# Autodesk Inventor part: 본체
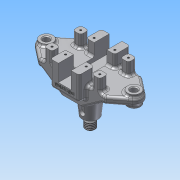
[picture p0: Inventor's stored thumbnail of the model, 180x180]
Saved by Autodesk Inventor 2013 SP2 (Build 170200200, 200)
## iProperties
Created: 2025-07
Part Number: 본체
Material: 알루미늄 6061
Document SubType Name: Modeling
Designer: a
Density: 2.71 g/cm^3
Mass: 328.836 g
Surface Area: 260.948 cm^2
Volume: 121.342 cm^3
Author: a
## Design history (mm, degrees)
sketch "스케치1"
  geometry: L1 (-41.804, 23)-(41.804, 23); L2 (41.804, 23)-(41.804, -23); L3 (41.804, -23)-(-41.804, -23); L4 (-41.804, -23)-(-41.804, 23); L5 (-41.804, 23)-(41.804, -23); L6 (41.804, 23)-(-41.804, -23); L7 (41.804, -23)-(61.157, -7.88); L8 (61.157, 7.88)-(41.804, 23); L9 (-41.804, -23)-(-61.157, -7.88); L10 (-41.804, 23)-(-61.157, 7.88); A1 r 10 centre (55, 0) between (61.157, -7.88) and (61.157, 7.88); A2 r 10 centre (-55, 0) between (-61.157, -7.88) and (-61.157, 7.88); 3 further points
  constraints: 20 end point, 4 midpoint, 4 point on circle, 4 tangent, 2 centre point, 2 horizontal alignment, 2 parallel, 1 horizontal, 1 perpendicular
  dimensions: "d0" = 46 distance of L3.end L1.start; "d4" = 110 distance of A2.centre A1.centre; "d5" = 55 distance of point (0, 0) A2.centre; "d6" = 76 deg angle of L10 L9; "d7" = 76 deg angle of L8 L7; "d8" = 20 diameter of A1
extrude "돌출1" new body sketch "스케치1" stored distance "d9" = 9; taper "d10" = 0 deg
sketch "스케치2"
  geometry: C1 r 8 at (-55, 0); C2 r 8 at (55, 0); A1 r 10 centre (-55, 0) between (-61.157, 7.88) and (-61.157, -7.88) reference; A2 r 10 centre (55, 0) between (61.157, -7.88) and (61.157, 7.88) reference; 1 further point
  constraints: 2 centre point, 2 coincident
  dimensions: "d11" = 16 diameter of C1; "d13" = 16 diameter of C2
extrude "돌출2" join sketch "스케치2" distance "d14" = 3; taper "d15" = 0 deg
extrude "돌출3" join sketch "스케치2" distance "d16" = 12; taper "d17" = 0 deg
hole "구멍1" diameter "d20" = 8; stored, may be unused: countersink angle "d24" = 90 deg, drill point angle "d26" = 118 deg; dims "d18" = 10, "d19" = 10, "d21" = 6, "d22" = 4, "d23" = 2, "d25" = 8
hole "구멍2" diameter "d29" = 8; stored, may be unused: countersink angle "d33" = 90 deg, drill point angle "d35" = 118 deg; dims "d27" = 10, "d28" = 10, "d30" = 6, "d31" = 4, "d32" = 2, "d34" = 8
chamfer "모따기1" distance "d36" = 1; stored, may be unused: second distance "d37" = 2, angle "d38" = 45 deg
chamfer "모따기2" distance "d39" = 1; stored, may be unused: second distance "d40" = 2, angle "d41" = 45 deg
chamfer "모따기3" distance "d42" = 1; stored, may be unused: second distance "d43" = 2, angle "d44" = 45 deg
chamfer "모따기4" distance "d45" = 1; stored, may be unused: second distance "d46" = 2, angle "d47" = 45 deg
sketch "스케치3"
  geometry: L1 (-41.804, -23)-(41.804, -23) reference; L2 (41.804, 23)-(-41.804, 23) reference; L3 (-35, -23)-(-25, -23); L4 (-25, -23)-(-25, -13); L5 (-25, -13)-(-35, -13); L6 (-35, -13)-(-35, -23); L7 (0, 23)-(0, -23); L8 (-55, 0)-(55, 0); L9 (-30, -13)-(-30, -23); L10 (-35, -18)-(-25, -18); L11 (61.157, -7.88)-(41.804, -23); L12 (25, -13)-(35, -13); L13 (35, -13)-(35, -23); L14 (35, -18)-(25, -18); L15 (30, -13)-(30, -23); L16 (25, -23)-(25, -13); L17 (35, -23)-(25, -23); L18 (41.804, -23)-(-41.804, -23); L19 (-25, 23)-(-25, 13); L20 (-30, 13)-(-30, 23); L21 (-25, 13)-(-35, 13); L22 (-35, 13)-(-35, 23); L23 (-35, 23)-(-25, 23); L24 (-35, 18)-(-25, 18); L25 (30, 13)-(30, 23); L26 (25, 13)-(35, 13); L27 (35, 13)-(35, 23); L28 (35, 18)-(25, 18); L29 (35, 23)-(25, 23); L30 (25, 23)-(25, 13); L31 (0, -23)-(0, 23); L32 (-41.804, 23)-(41.804, 23); L33 (41.804, 23)-(-41.804, 23); A1 r 10 centre (-55, 0) between (-61.157, 7.88) and (-61.157, -7.88) reference; A2 r 10 centre (55, 0) between (61.157, -7.88) and (61.157, 7.88) reference; 1 further point
  constraints: 62 end point, 32 symmetric about line, 6 midpoint, 4 point on line, 2 parallel, 2 perpendicular, 1 horizontal
  dimensions: "d48" = 10 distance of L4.end L5.end; "d50" = 10 distance of L3.end L4.end; "d51" = 30 distance between parallel lines of L7 L9
extrude "돌출4" join sketch "스케치3" distance "d52" = 16; taper "d53" = 0 deg
sketch "스케치4"
  geometry: L1 (-18, 32)-(18, 32); L2 (18, 32)-(18, 13); L3 (18, 13)-(-18, 13); L4 (-18, 13)-(-18, 32); L5 (-18, -13)-(18, -13); L6 (18, -13)-(18, -32); L7 (18, -32)-(-18, -32); L8 (-18, -32)-(-18, -13); 3 further points
  constraints: 16 end point, 4 parallel, 2 horizontal, 2 midpoint, 2 perpendicular, 2 vertical alignment
  dimensions: "d54" = 36 distance of L1.start L1.end; "d56" = 36 distance of L6.end L7.end; "d57" = 64 distance between parallel lines of L7 L1; "d58" = 32 distance of point (0, 0) point (0, 32); "d59" = 26 distance between parallel lines of L5 L3; "d60" = 13 distance from line of point (0, 0) L3
extrude "돌출5" join sketch "스케치4" distance "d61" = 16; taper "d63" = 0 deg; dims "d62" = 15, "d64" = 0
sketch "스케치5"
  geometry: L1 (0, 0)-(36, 0) reference; L2 (10, 0)-(26, 0); L3 (26, 0)-(26, -21); L4 (26, -21)-(10, -21); L5 (10, -21)-(10, 0); 2 further points
  constraints: 8 end point, 2 midpoint, 2 parallel, 1 horizontal, 1 perpendicular, 1 vertical alignment
  dimensions: "d65" = 16 distance of L2.start L2.end; "d67" = 21 distance of L4.end L2.start
extrude "돌출6" cut sketch "스케치5" stored distance "d68" = 16; taper "d69" = 0 deg
sketch "스케치6"
  geometry: L1 (60, -7.5)-(59, -6.5) reference; L2 (59, -6.5)-(59, 6.5) reference; L3 (59, 6.5)-(60, 7.5) reference; L4 (60, 7.5)-(63, 7.5) reference; L5 (63, 7.5)-(63, 4.5) reference; L6 (63, 4.5)-(65, 4.5) reference; L7 (65, 4.5)-(65, -4.5) reference; L8 (65, -4.5)-(63, -4.5) reference; L9 (63, -4.5)-(63, -7.5) reference; L10 (63, -7.5)-(60, -7.5) reference; L11 (-59, -6.5)-(-60, -7.5) reference; L12 (-60, -7.5)-(-63, -7.5) reference; L13 (-63, -7.5)-(-63, -4.5) reference; L14 (-63, -4.5)-(-65, -4.5) reference; L15 (-65, -4.5)-(-65, 4.5) reference; L16 (-65, 4.5)-(-63, 4.5) reference; L17 (-63, 4.5)-(-63, 7.5) reference; L18 (-63, 7.5)-(-60, 7.5) reference; L19 (-60, 7.5)-(-59, 6.5) reference; L20 (-59, 6.5)-(-59, -6.5) reference; L21 (-50, -7.5)-(-51, -6.5) reference; L22 (-51, -6.5)-(-51, 6.5) reference; L23 (-51, 6.5)-(-50, 7.5) reference; L24 (-50, 7.5)-(-47, 7.5) reference; L25 (-47, 7.5)-(-47, 4.5) reference; L26 (-47, 4.5)-(-8, 4.5) reference; L27 (-8, 4.5)-(-8, -0.5) reference; L28 (-8, -0.5)-(8, -0.5) reference; L29 (8, -0.5)-(8, 4.5) reference; L30 (8, 4.5)-(47, 4.5) reference; L31 (47, 4.5)-(47, 7.5) reference; L32 (47, 7.5)-(50, 7.5) reference; L33 (50, 7.5)-(51, 6.5) reference; L34 (51, 6.5)-(51, -6.5) reference; L35 (51, -6.5)-(50, -7.5) reference; L36 (50, -7.5)-(47, -7.5) reference; L37 (47, -7.5)-(47, -4.5) reference; L38 (47, -4.5)-(-47, -4.5) reference; L39 (-47, -4.5)-(-47, -7.5) reference; L40 (-47, -7.5)-(-50, -7.5) reference; L41 (-38.85, -4.5)-(-16, -20.5); L42 (-16, -20.5)-(16, -20.5); L43 (16, -20.5)-(38.85, -4.5); L44 (25, 20.5)-(35, 20.5) reference; L45 (-38.85, -4.5)-(38.85, -4.5); 2 further points
  constraints: 8 end point, 2 point on line, 1 collinear, 1 midpoint, 1 parallel, 1 vertical alignment
  dimensions: "d70" = 41 distance between parallel lines of L44 L42; "d71" = 35 deg angle of L42 L43; "d72" = 35 deg angle of L42 L41; "d73" = 32 distance of L41.end L42.end
extrude "돌출7" join sketch "스케치6" stored distance "d74" = 46; taper "d75" = 0 deg
sketch "스케치7"
  geometry: L1 (-10.5, 23)-(-10.5, 32) reference; L2 (-10.5, 32)-(-0.5, 32) reference; L3 (-0.5, 32)-(-0.5, -32) reference; L4 (-0.5, -32)-(-10.5, -32) reference; L5 (-10.5, -32)-(-10.5, -23) reference; L6 (-10.5, -23)-(-20.5, -23) reference; L7 (-20.5, -23)-(-20.5, 23) reference; L8 (-20.5, 23)-(-10.5, 23) reference; L9 (-20.5, 0)-(-47.5, 0); L10 (-20.5, 12.5)-(-24.5, 12.5); L11 (-24.5, 12.5)-(-47.5, 10); L12 (-47.5, 10)-(-47.5, 0); L13 (-20.5, 12.5)-(-20.5, 0); 1 further point
  constraints: 10 end point, 3 parallel, 1 midpoint, 1 perpendicular, 1 point on line
  dimensions: "d76" = 25 diameter of L10 L9; "d78" = 4 distance of L10.start L10.end; "d79" = 23 horizontal distance of L11.end L10.end; "d80" = 20 diameter of L11.end L9
revolve "회전1" sketch "스케치7" stored, may be unused: angle "d81" = 90 deg
sketch "스케치8"
  geometry: L1 (-10.5, 23)-(-10.5, 32) reference; L2 (-10.5, 32)-(-0.5, 32) reference; L3 (-0.5, 32)-(-0.5, -32) reference; L4 (-0.5, -32)-(-10.5, -32) reference; L5 (-10.5, -32)-(-10.5, -23) reference; L6 (-10.5, -23)-(-20.5, -23) reference; L7 (-20.5, -23)-(-20.5, -12.5) reference; L8 (-20.5, -12.5)-(-24.5, -12.5) reference; L9 (-24.5, -12.5)-(-47.5, -10) reference; L10 (-47.5, -10)-(-47.5, 10) reference; L11 (-47.5, 10)-(-24.5, 12.5) reference; L12 (-24.5, 12.5)-(-20.5, 12.5) reference; L13 (-20.5, 12.5)-(-20.5, 23) reference; L14 (-20.5, 23)-(-10.5, 23) reference; L15 (-47.5, 0)-(-61.5, 0); L16 (-47.5, 0)-(-47.5, 4.7); L17 (-47.5, 4.7)-(-50.5, 4.7); L18 (-50.5, 4.7)-(-52.752, 6); L19 (-52.752, 6)-(-61.5, 6); L20 (-61.5, 6)-(-61.5, 0); 1 further point
  constraints: 12 end point, 2 parallel, 2 perpendicular, 1 midpoint, 1 point on line
  dimensions: "d82" = 3 distance of L16.end L17.end; "d84" = 30 deg angle of L19 L18; "d86" = 9.4 diameter of L17 L15; "d87" = 41 distance between parallel lines of L13 L20; "d89" = 12 diameter of L19 L15
revolve "회전2" sketch "스케치8" stored, may be unused: angle "d90" = 90 deg
chamfer "모따기5" distance "d91" = 1; stored, may be unused: second distance "d92" = 2, angle "d93" = 45 deg
feature "스레드1" dims "d94" = 10, "d95" = 0
sketch "스케치9"
  geometry: L1 (-10.5, 23)-(-10.5, 32) reference; L2 (-10.5, 32)-(-0.5, 32) reference; L3 (-0.5, 32)-(-0.5, -32) reference; L4 (-0.5, -32)-(-10.5, -32) reference; L5 (-10.5, -32)-(-10.5, -23) reference; L6 (-10.5, -23)-(-20.5, -23) reference; L7 (-20.5, -23)-(-20.5, -12.5) reference; L8 (-20.5, -12.5)-(-24.5, -12.5) reference; L9 (-24.5, -12.5)-(-47.5, -10) reference; L10 (-47.5, -10)-(-47.5, -4.7) reference; L11 (-47.5, -4.7)-(-50.5, -4.7) reference; L12 (-50.5, -4.7)-(-52.752, -6) reference; L13 (-52.752, -6)-(-60.5, -6) reference; L14 (-60.5, -6)-(-61.5, -5) reference; L15 (-61.5, -5)-(-61.5, 5) reference; L16 (-61.5, 5)-(-60.5, 6) reference; L17 (-60.5, 6)-(-52.752, 6) reference; L18 (-52.752, 6)-(-50.5, 4.7) reference; L19 (-50.5, 4.7)-(-47.5, 4.7) reference; L20 (-47.5, 4.7)-(-47.5, 10) reference; L21 (-47.5, 10)-(-24.5, 12.5) reference; L22 (-24.5, 12.5)-(-20.5, 12.5) reference; L23 (-20.5, 12.5)-(-20.5, 23) reference; L24 (-20.5, 23)-(-10.5, 23) reference; L25 (-27.617, 12.161)-(-27.185, 8.185); L26 (-27.185, 8.185)-(-43.091, 6.456); L27 (-43.091, 6.456)-(-43.523, 10.432); L28 (-27.617, 12.161)-(-43.523, 10.432); 1 further point
  constraints: 8 end point, 2 perpendicular, 2 point on line, 1 collinear, 1 parallel
  dimensions: "d96" = 4 distance between parallel lines of L21 L26; "d97" = 16 distance between parallel lines of L27 L25; "d98" = 4 distance from line of L20.end L27
extrude "돌출8" cut sketch "스케치9" stored distance "d99" = 7; taper "d100" = 0 deg
fillet "모깎기1" dims "d101" = 3.5
fillet "모깎기2" dims "d102" = 3
fillet "모깎기3" dims "d103" = 3
fillet "모깎기4" dims "d104" = 3
fillet "모깎기6" dims "d106" = 3
fillet "모깎기7" dims "d107" = 3
fillet "모깎기8" dims "d108" = 3
fillet "모깎기9" dims "d109" = 3
fillet "모깎기10" dims "d110" = 3
fillet "모깎기11" dims "d111" = 3
fillet "모깎기12" dims "d112" = 3
fillet "모깎기13" dims "d113" = 3
fillet "모깎기14" dims "d114" = 3
fillet "모깎기15" dims "d115" = 3
sketch "스케치10"
  geometry: 2 further points
  dimensions: "d116" = 13 horizontal distance of point (0, 0) point (-13, -18); "d117" = 18 vertical distance of point (-13, -18) point (0, 0)
hole "구멍3" sketch "스케치10" at (-13, -18) diameter "d118" = 2.459; stored, may be unused: countersink angle "d122" = 90 deg, drill point angle "d124" = 118 deg; dims "d119" = 6, "d120" = 4, "d121" = 2, "d123" = 8
sketch "스케치11"
  geometry: L1 (-25, -20)-(-25, -16) reference; L2 (-28, -13)-(-32, -13) reference; 2 further points
  dimensions: "d131" = 5 distance from line of L1 point (-30, -18); "d132" = 5 distance from line of L2 point (-30, -18)
hole "구멍4" sketch "스케치11" at (-30, -18) diameter "d133" = 2.459; stored, may be unused: countersink angle "d137" = 90 deg, drill point angle "d139" = 118 deg; dims "d134" = 6, "d135" = 4, "d136" = 2, "d138" = 8
fillet "모깎기16" dims "d140" = 3
sketch "스케치12"
  geometry: L1 (16, 0)-(0, 0) reference; L2 (-7, 21)-(0, 21) reference; 3 further points
  constraints: 1 midpoint, 1 vertical alignment, 1 other
  dimensions: "d141" = 24 distance from line of L2 point (8, -3)
feature "엠보싱1" sketch "스케치12" dims "d4" = 110, "d142" = 0.5, "d143" = 0
node "솔리드1"
pattern_linear "직사각형 패턴1" dims "d127" = 26
pattern_linear "직사각형 패턴2" dims "d130" = 36
mirror "대칭1"
mirror "대칭2"
node "절단 모서리 투영1"
node "절단 모서리 투영2"
node "절단 모서리 투영3"
node "절단 모서리 투영4"
